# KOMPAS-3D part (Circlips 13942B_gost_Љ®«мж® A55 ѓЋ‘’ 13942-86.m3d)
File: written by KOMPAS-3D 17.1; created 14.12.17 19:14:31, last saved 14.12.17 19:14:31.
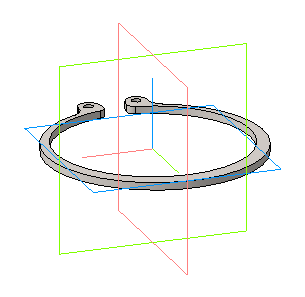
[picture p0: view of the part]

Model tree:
1. Операция без истории:1  (labels: Circlips 13942B_gost_Љ®«мж® A55 ѓЋ‘’ 13942-86)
